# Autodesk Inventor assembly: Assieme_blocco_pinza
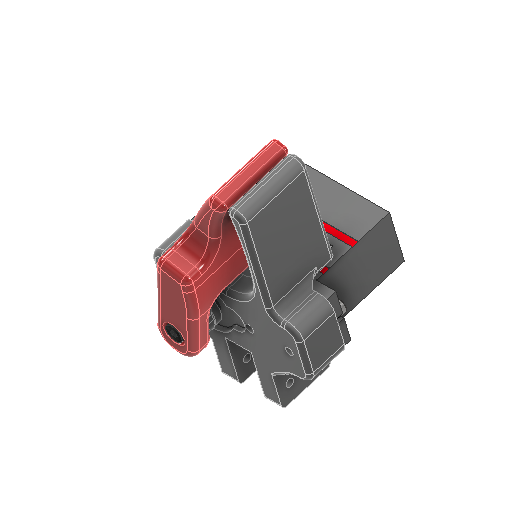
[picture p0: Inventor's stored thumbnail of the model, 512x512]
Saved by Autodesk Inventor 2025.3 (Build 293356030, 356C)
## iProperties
Created: 2026-03
Part Number: Assieme_blocco_pinza
Document SubType Name: Assembly
Designer: R5800u
Author: R5800u
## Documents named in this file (7)
- C:\Users\R5800u\Desktop\mini_robot_RCXAZ_9g\Assieme_pinza.iam
- C:\Users\R5800u\Desktop\mini_robot_RCXAZ_9g\blocco_pinza_eco_orizzontale_b.ipt
- C:\Users\R5800u\Desktop\mini_robot_RCXAZ_9g\dito_pinza_mg90s.ipt
- C:\Users\R5800u\Documents\Inventor\Content Center Files\R2025\it-IT\ISO 14580_2011(E)\ISO 14580 M2x8-4.8.ipt
- C:\Users\R5800u\Documents\Inventor\Content Center Files\R2025\it-IT\ANSI B18.3.1M(6)\ANSI B18.3.1M - M1,6x0,35 x 8(1).ipt
- C:\Users\R5800u\Desktop\mini_robot_RCXAZ_9g\RCXAZ_9g.ipt
- C:\Users\R5800u\Desktop\mini_robot_RCXAZ_9g\RCXAZ_9g singolo.ipt
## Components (7 placed, 6 different names)
1. blocco_pinza_eco_orizzontale_b:1 — Coincidente:13, Coincidente:14, Coincidente:18
2. dito_pinza_mg90s:1 — Coincidente:19, Coincidente:20, Coincidente:21, Angolo:1, Rotazionale:2
3. Vite forgiata a testa incassata - Metrico M1,6x0,35 x 8:1 — Coincidente:17
4. Vite forgiata a testa incassata - Metrico M1,6x0,35 x 8:2 — Coincidente:16
5. RCXAZ_9g:1 — Coincidente:13, Coincidente:14, Coincidente:16, Coincidente:17, Coincidente:18, Rotazionale:1, Coincidente:19, Coincidente:20
6. RCXAZ_9g singolo:1 — Rotazionale:1, Coincidente:21, Angolo:1
7. Vite ISO 14580:2011(E) M2x8-4.8:1 — Rotazionale:2
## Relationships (11: Mate 8, RevoluteJoint 2, Angle 1)
- Coincidente:13 [Mate]: blocco_pinza_eco_orizzontale_b:1 ↔ RCXAZ_9g:1
- Coincidente:14 [Mate]: blocco_pinza_eco_orizzontale_b:1 ↔ RCXAZ_9g:1
- Coincidente:16 [Mate]: Vite forgiata a testa incassata - Metrico M1,6x0,35 x 8:2 ↔ RCXAZ_9g:1
- Coincidente:17 [Mate]: Vite forgiata a testa incassata - Metrico M1,6x0,35 x 8:1 ↔ RCXAZ_9g:1
- Coincidente:18 [Mate]: blocco_pinza_eco_orizzontale_b:1 ↔ RCXAZ_9g:1
- Rotazionale:1 [RevoluteJoint]: RCXAZ_9g:1 ↔ RCXAZ_9g singolo:1
- Coincidente:19 [Mate]: dito_pinza_mg90s:1 ↔ RCXAZ_9g:1
- Coincidente:20 [Mate]: dito_pinza_mg90s:1 ↔ RCXAZ_9g:1
- Coincidente:21 [Mate]: dito_pinza_mg90s:1 ↔ RCXAZ_9g singolo:1
- Angolo:1 [Angle]: dito_pinza_mg90s:1 ↔ RCXAZ_9g singolo:1
- Rotazionale:2 [RevoluteJoint]: dito_pinza_mg90s:1 ↔ Vite ISO 14580:2011(E) M2x8-4.8:1
